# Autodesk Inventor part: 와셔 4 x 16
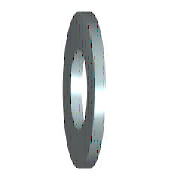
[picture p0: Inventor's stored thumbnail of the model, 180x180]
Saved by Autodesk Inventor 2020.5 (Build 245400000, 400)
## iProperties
IsCustomPart: 1
Created: 2012-02
Part Number: 와셔 4 x 16
Material: 강철, 연강
Description: 미터법 평면 와셔
Document SubType Name: Modeling
Standard: ANSI B18.22M
Designer: mduedu
Standard Revision: 1999
Standards Organization: ANSI
Language: ko-KR
Size Designation: 4 W
Categories: <MemberInstance><Categories><Category DisplayName="조임쇠" InternalName="e4da775c-781d-43d5-af7c-5136215cf5a6" Mnemonic="FSTN"><Category DisplayName="와셔" InternalN
Density: 1 g/cm^3
Appearance: 파란색 - 벽 페인트 - 광택
Author: mduedu
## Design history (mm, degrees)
sketch "스케치"
  geometry: C1 r 8 at (0, 0); C2 r 2.35 at (0, 0); 1 further point
  constraints: 2 centre point, 2 coincident
  dimensions: "d0" = 4.7 diameter of C2 (= SD1); "d1" = 16 diameter of C1 (= SD2)
extrude "본체" new body sketch "스케치" distance "d2" = 2.3 (= SD); taper "d3" = 0 deg
workaxis "Work Axis1"
workplane "Work Plane1"
body "Solid1"
other parameters: "SD1" = 4.7 [user parameter; used in 1 equation term], "SD2" = 16 [user parameter; used in 1 equation term], "SD" = 2.3 [user parameter; used in 1 equation term], "d4" = 0, "d5" = 0, "d6" = 0, "d7" = 0, "NND" = 4 [user parameter]
